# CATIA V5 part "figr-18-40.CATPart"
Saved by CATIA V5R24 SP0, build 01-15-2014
Part number: Part1
Bounding box of the stored display mesh (mm): x -198 to 20, y -85 to 85, z 0 to 0
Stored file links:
  D:\KAVITA\CATIA V5-6R2014 Project_ Kavita\CATIA V5-6R2014_partfiles\Partfiles\c17_caia_v6-6r2014_prt\figr-17-40.CATPart
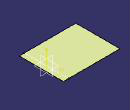
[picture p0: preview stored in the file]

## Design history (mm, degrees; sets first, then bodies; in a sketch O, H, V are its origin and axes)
Body1 (main body)
  Sketch1 on yz-plane, origin (0, 0, 0), H (0, 1, 0), V (0, 0, 1)
    line L1 (-85, 0) -> (85, 0)
    point P1 (-85, 0)
    coincidence: P1 H
    horizontal: L1 H
  Extrude1: Lim1 20, Lim2 198, Element1 Sketch1
  DatumSurface1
